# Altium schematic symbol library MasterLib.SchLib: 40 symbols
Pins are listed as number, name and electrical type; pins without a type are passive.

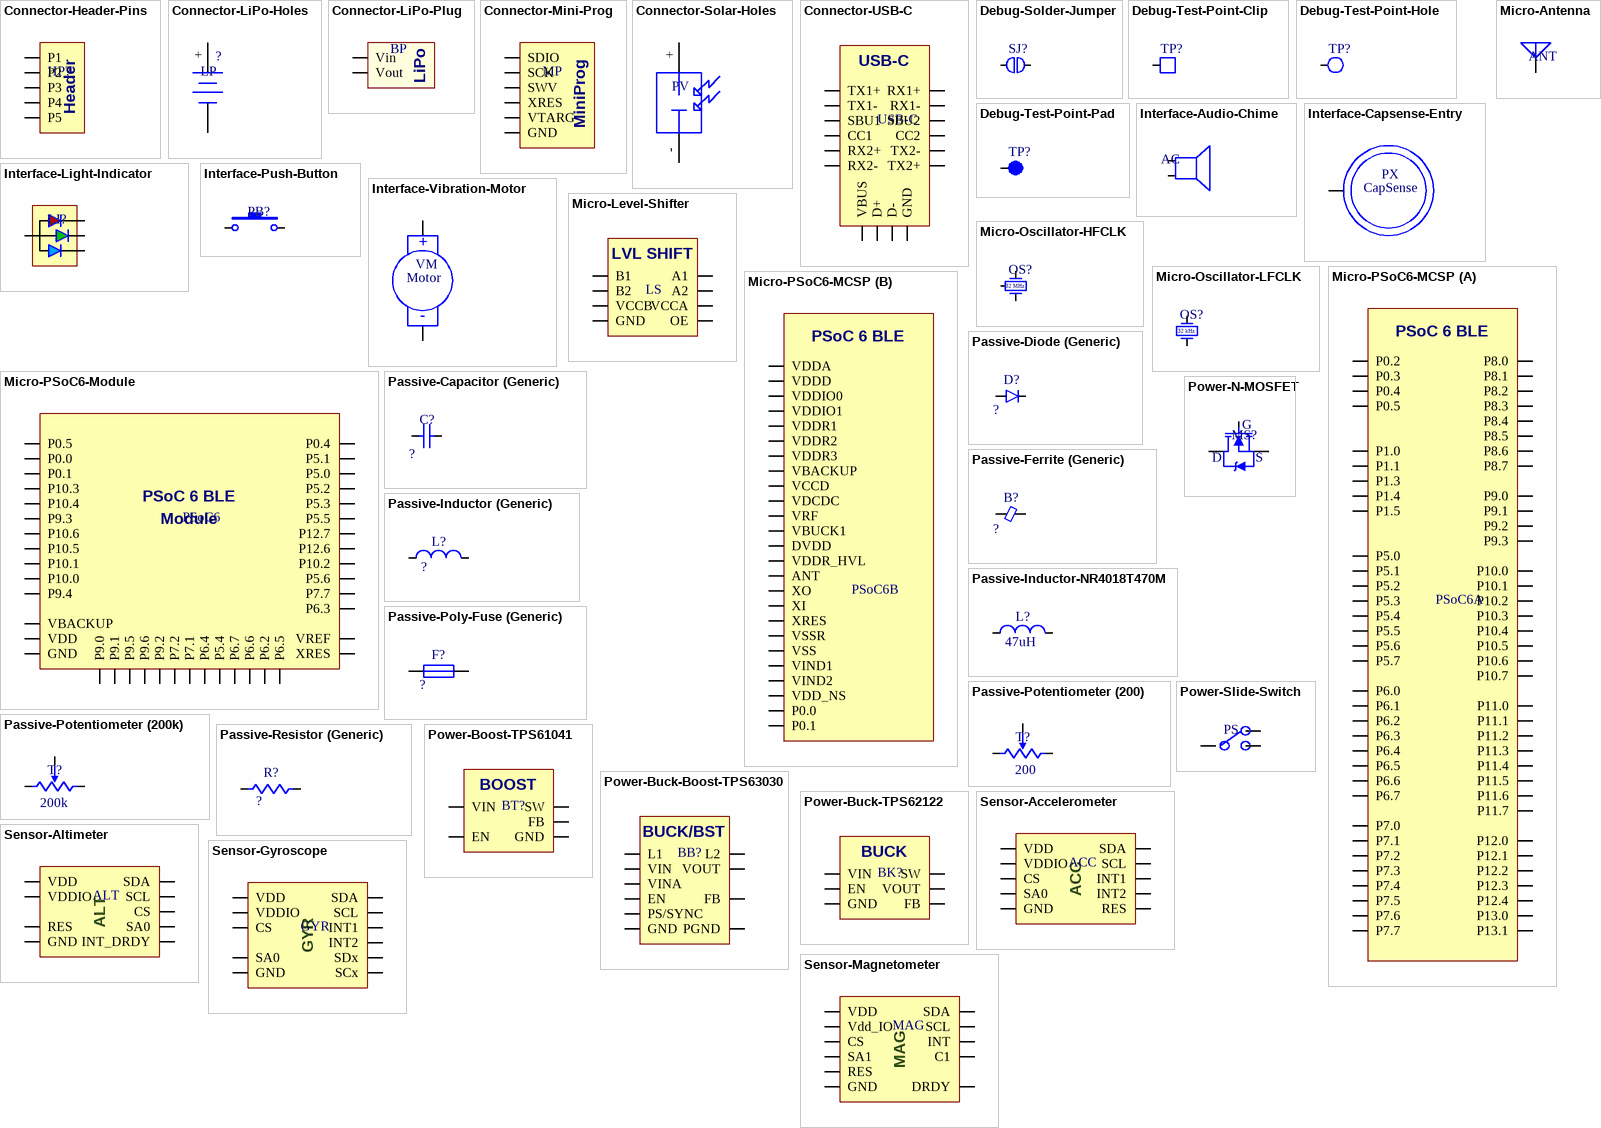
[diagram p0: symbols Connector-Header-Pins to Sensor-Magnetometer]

## Connector-Header-Pins
designator HP?  (value not drawn)
2.54mm Pitch, 5 Pin, 1 Row, SMD, Header Pin; Manufacturer: TE Connectivity; Manufacturer Part Number: 1-146132-3; Value: 5 Pin; Through Hole (y/n): N
footprint CONNECTOR-HEADER-PINS
pins: 1 P1, 2 P2, 3 P3, 4 P4, 5 P5

## Connector-LiPo-Holes
designator LP  (value not drawn)
Thru Hole for LiPo; Through Hole (y/n): Y
footprint CONNECTOR-LIPO-HOLES
pins: +, -

## Connector-LiPo-Plug
designator BP  (value not drawn)
Standard battery plug female
footprint CONNECTOR-LIPO-PLUG
pins: Vin, Vout

## Connector-Mini-Prog
designator MP  (value not drawn)
1.27mm Pitch, 2x5 Pin, Shrouded, Male Header; Manufacturer: Samtec; Manufacturer Part Number: FTSH-105-01-L-DV-K; Value: 10 Pin; Through Hole (y/n): N
footprint CONNECTOR-MINI-PROG
pins: GND, SCK, SDIO, SWV, VTARG, XRES

## Connector-Solar-Holes
designator PV  (value not drawn)
Solar Cell Pads; Through Hole (y/n): Y
footprint CONNECTOR-SOLAR-HOLES
pins: +, -

## Connector-USB-C
designator USB-C  (value not drawn)
USB-C 3.1 Receptacle Connector, 24 Position Surface Mount, Right Angle; Manufacturer: Amphenol; Manufacturer Part Number: 12401598E4#2A; Through Hole (y/n): N
footprint CONNECTOR-USB-C
pins: CC1, CC2, D+, D-, GND, RX1+, RX1-, RX2+, RX2-, SBU1, SBU2, TX1+, TX1-, TX2+, TX2-, VBUS

## Debug-Solder-Jumper
designator SJ?  (value not drawn)  (no BOM)
3.5mm Diameter, Solder Jumper Pad
footprint DEBUG-SOLDER-JUMPER
pins: 1, 2

## Debug-Test-Point-Clip
designator TP?  (value not drawn)  (no BOM)
Test point loop clip; Manufacturer: Keystone Electronics; Manufacturer Part Number: 5019; Through Hole (y/n): N
footprint DEBUG-TEST-POINT-CLIP (Keystone, 5019)
pins: 1

## Debug-Test-Point-Hole
designator TP?  (value not drawn)  (no BOM)
2.54 inch header pin hole
footprint DEBUG-TEST-POINT-HOLE
pins: 1

## Debug-Test-Point-Pad
designator TP?  (value not drawn)  (no BOM)
1.5mm, Single Sided, Test Point Pad
footprint DEBUG-TEST-POINT-PAD
pins: 1

## Interface-Audio-Chime
designator AC  (value not drawn)
9kHz Freq, 12mm Diameter, Piezoelectric Diaphram; Manufacturer: Murata; Manufacturer Part Number: 7BB-12-9; Through Hole (y/n): N
footprint INTERFACE-AUDIO-CHIME
pins: 1, 2

## Interface-Capsense-Entry
designator PX  (value not drawn)  (no BOM)
Single Pin CapSense Entry Point
footprint INTERFACE-CAPSENSE-ENTRY
pins: 1

## Interface-Light-Indicator
designator LI?  (value not drawn)
0606, RGB, White Diffused, SMD, Light Indicator; Manufacturer: Lite-On; Manufacturer Part Number: LTST-C19HE1WT; Through Hole (y/n): N
footprint INTERFACE-LIGHT-INDICATOR
pins: +, B-, G-, R-

## Interface-Push-Button
designator PB?  (value not drawn)
2.5mm Tall, 2.5N Force, Straight, SMD, Push Button; Manufacturer: C&K Components; Manufacturer Part Number: PTS820 J25K SMTR LFS; Value: Single; Through Hole (y/n): N
footprint INTERFACE-PUSH-BUTTON
pins: 1, 2

## Interface-Vibration-Motor
designator VM  (value not drawn)
15k RPM, 2.7V, 3mm Height, SMD, Vibration Motor; Manufacturer: Jinlong Machinery; Manufacturer Part Number: Z30C1T8460001; Value: 15k RPM; Through Hole (y/n): N
footprint INTERFACE-VIBRATION-MOTOR
pins: +, -

## Micro-Antenna
designator ANT  (value not drawn)
2.45GHz, 50 ohm, SMD, Ceramic Chip Antenna; Manufacturer: Johanson; Manufacturer Part Number: 2450AT18A100; Value: 2.45 MHz; Through Hole (y/n): N
footprint MICRO-ANTENNA
pins: FEED

## Micro-Level-Shifter
designator LS  (value not drawn)
2-Bit, Bi-Directional, Voltage Level Translator; Manufacturer: Texas Instruments; Manufacturer Part Number: TXS0102YZPR; Value: Dual; Through Hole (y/n): N
footprint MICRO-LEVEL-SHIFTER
pins: A1, A2, B1, B2, GND, OE, VCCA, VCCB

## Micro-Oscillator-HFCLK
designator OS?  (value not drawn)
32MHz, 10ppm, 8pF, Crystal Oscillator; Manufacturer: ECS Inc.; Manufacturer Part Number: ECS-320-8-36CKM-TR; Through Hole (y/n): N
footprint MICRO-OSCILLATOR-HFCLK
pins: GND, In/Out, Out/In

## Micro-Oscillator-LFCLK
designator OS?  (value not drawn)
32.768kHz, 20ppm, 12.5pF, Crystal Oscillator; Manufacturer: ECS Inc.; Manufacturer Part Number: ECS-.327-12.5-34B-TR; Through Hole (y/n): N
footprint MICRO-OSCILLATOR-LFCLK
pins: 1 OSC1, 2 OSC2

## Micro-PSoC6-MCSP
designator PSoC6  (value not drawn)
PSoC 6 BLE 104-MCSP; Manufacturer: Cypress; Through Hole (y/n): N
footprint MICRO-PSOC6-MCSP
part A pins: P0.2, P0.3, P0.4, P0.5, P1.0, P1.1, P1.3, P1.4, P1.5, P5.0, P5.1, P5.2, P5.3, P5.4, P5.5, P5.6, P5.7, P6.0, P6.1, P6.2, P6.3, P6.4, P6.5, P6.6, P6.7, P7.0, P7.1, P7.2, P7.3, P7.4, P7.5, P7.6, P7.7, P8.0, P8.1, P8.2, P8.3, P8.4, P8.5, P8.6, P8.7, P9.0, P9.1, P9.2, P9.3, P10.0, P10.1, P10.2, P10.3, P10.4, P10.5, P10.6, P10.7, P11.0, P11.1, P11.2, P11.3, P11.4, P11.5, P11.6, P11.7, P12.0, P12.1, P12.2, P12.3, P12.4, P13.0, P13.1
part B pins: ANT, DVDD, P0.0, P0.1, VBACKUP, VBUCK1, VCCD, VDCDC, VDD_NS, VDDA, VDDD, VDDIO0, VDDIO1, VDDR1, VDDR2, VDDR3, VDDR_HVL, VIND1, VIND2, VRF, VSS, VSSR, XI, XO, XRES

## Micro-PSoC6-Module
designator PSoC6  (value not drawn)
PSoC 6 BLE Module; Manufacturer: Cypress; Manufacturer Part Number: CYBLE-416045-02; Through Hole (y/n): N
footprint MICRO-PSOC6-MODULE
pins: GND, P0.0, P0.1, P0.4, P0.5, P5.0, P5.1, P5.2, P5.3, P5.4, P5.5, P5.6, P6.2, P6.3, P6.4, P6.5, P6.6, P6.7, P7.1, P7.2, P7.7, P9.0, P9.1, P9.2, P9.3, P9.4, P9.5, P9.6, P10.0, P10.1, P10.2, P10.3, P10.4, P10.5, P10.6, P12.6, P12.7, VBACKUP, VDD, VREF, XRES

## Passive-Capacitor (Generic)
designator C?  (value not drawn)
Generic Capacitor
footprint PASSIVE-CAPACITOR-0603
footprint PASSIVE-CAPACITOR-0805
footprint PASSIVE-CAPACITOR-0402
pins: 1, 2

## Passive-Diode (Generic)
designator D?  (value not drawn)
Generic Diode; Through Hole (y/n): N
footprint PASSIVE-DIODE-0402
footprint PASSIVE-DIODE-0603
footprint PASSIVE-DIODE-0805
pins: +, -

## Passive-Ferrite (Generic)
designator B?  (value not drawn)
Generic Ferrite Bead
footprint PASSIVE-FERRITE-BEAD-0805
footprint PASSIVE-FERRITE-BEAD-0402
footprint PASSIVE-FERRITE-BEAD-0603
pins: 1, 2

## Passive-Inductor (Generic)
designator L?  (value not drawn)
Generic Inductor
footprint PASSIVE-INDUCTOR-0805
footprint PASSIVE-INDUCTOR-0603
footprint PASSIVE-INDUCTOR-0402
pins: 1, 2

## Passive-Inductor-NR4018T470M
designator L?  value 47uH  (hidden comment: *)
47 uH, 420mA; Manufacturer: Taiyo Yuden; Manufacturer Part Number: NR4018T470M; Through Hole (y/n): N
footprint PASSIVE-INDUCTOR-NR4018T470M
pins: 1, 2

## Passive-Poly-Fuse (Generic)
designator F?  (value not drawn)
Generic Poly Fuse; Through Hole (y/n): N
footprint PASSIVE-POLY-FUSE-0402
footprint PASSIVE-POLY-FUSE-0603
footprint PASSIVE-POLY-FUSE-0805
pins: 1, 2

## Passive-Potentiometer (200)
designator T?  value 200  (hidden comment: *)
200 ohm, Single Turn, SMD, Potentiometer; Manufacturer Part Number: TC33X-2-201G; Manufacturer: Bourns; Through Hole (y/n): N
footprint PASSIVE-POTENTIOMETER
pins: 1, 2, wiper

## Passive-Potentiometer (200k)
designator T?  value 200k  (hidden comment: *)
200 kOhm, Single Turn, SMD, Potentiometer; Manufacturer Part Number: TC33X-2-204E; Manufacturer: Bourns; Through Hole (y/n): N
footprint PASSIVE-POTENTIOMETER
pins: 1, 2, wiper

## Passive-Resistor (Generic)
designator R?  (value not drawn)
Generic Resistor; Through Hole (y/n): N
footprint PASSIVE-RESISTOR-0603
footprint PASSIVE-RESISTOR-0805
footprint PASSIVE-RESISTOR-0402
pins: 1, 2

## Power-Boost-TPS61041
designator BT?  (value not drawn)
250mA, 1.8-28V Out, 1.8-6V In, 1kHz, Boost; Manufacturer: Texas Instruments; Manufacturer Part Number: TPS61041DBVR; Through Hole (y/n): N
footprint POWER-BOOST-TPS61041
pins: EN, FB, GND, SW, VIN

## Power-Buck-Boost-TPS63030
designator BB?  (value not drawn)
Buck-Boost Switching Regulator IC Positive Adjustable 1.2V 1 Output 900mA (Switch) 10-WFDFN Exposed Pad; Manufacturer: Texas Instruments; Manufacturer Part Number: TPS63030DSKR; Through Hole (y/n): N
footprint POWER-BUCK-BOOST-TPS63030
pins: EN, FB, GND, L1, L2, PGND, PS/SYNC, VIN, VINA, VOUT

## Power-Buck-TPS62122
designator BK?  (value not drawn)
Buck Switching Regulator IC Positive Adjustable 1.2V 1 Output 75mA 6-WDFN Exposed Pad; Manufacturer: Texas Instruments; Manufacturer Part Number: TPS62122DRVR; Through Hole (y/n): N
footprint POWER-BUCK-TPS62122
pins: EN, FB, GND, SW, VIN, VOUT

## Power-N-MOSFET
designator MS?  (value not drawn)
N-Channel, Power MOSFET; Manufacturer Part Number: DMN1019USN-7; Manufacturer: Diodes Incorporated; Through Hole (y/n): N
footprint POWER-N-MOSFET
pins: D, G, S

## Power-Slide-Switch
designator PS  (value not drawn)
DPDT, 300mA, 6V, SMD, Slide Switch; Manufacturer: Wurth Electronics; Manufacturer Part Number: 452403012014; Through Hole (y/n): N
footprint POWER-SLIDE-SWITCH
pins: 1, 2, 3

## Sensor-Accelerometer
designator ACC  (value not drawn)
16bit, 256 FIFO, 1.62-1.98V, I2C 400kHz; Manufacturer: STMicroelectronics; Manufacturer Part Number: LIS2DS12TR; Through Hole (y/n): N; Value: 16-bit
footprint SENSOR-ACCELEROMETER
pins: CS, GND, INT1, INT2, RES, SA0, SCL, SDA, VDD, VDDIO

## Sensor-Altimeter
designator ALT  (value not drawn)
24bit, 32 FIFO, 1.7-3.6V, I2C 400kHz; Manufacturer: ST Microelectronics; Manufacturer Part Number: LPS22HB; Through Hole (y/n): N; Value: 24-bit
footprint SENSOR-ALTIMETER
pins: CS, GND, INT_DRDY, RES, SA0, SCL, SDA, VDD, Vdd_IO VDDIO

## Sensor-Gyroscope
designator GYR  (value not drawn)
16bit, 4KB FIFO, 1.71-3.6V, I2C 400kHz; Manufacturer: STMicroelectronics; Manufacturer Part Number: LSM6DSLTR; Through Hole (y/n): N; Value: 16-bit
footprint SENSOR-GYROSCOPE
pins: CS, GND, INT1, INT2, SA0, SCL, SCx, SDA, SDx, VDD, VDDIO

## Sensor-Magnetometer
designator MAG  (value not drawn)
16bit, No FIFO, 1.9-3.6V, I2C 400kHz; Manufacturer: STMicroelectronics; Manufacturer Part Number: LIS3MDLTR; Through Hole (y/n): N; Value: 16-bit
footprint SENSOR-MAGNETOMETER
pins: C1, CS, DRDY, GND, INT, RES, SA1, SCL, SDA, VDD, VDDIO Vdd_IO

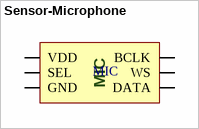
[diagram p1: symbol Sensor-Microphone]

## Sensor-Microphone
designator MIC  (value not drawn)
24bit, No FIFO, 1.62-3.6V, I2S 4096kHz; Manufacturer: Knowles; Manufacturer Part Number: SPH0645LM4H-B; Through Hole (y/n): N; Value: 18-bit
footprint SENSOR-MICROPHONE
pins: BCLK, DATA, GND, SEL, VDD, WS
